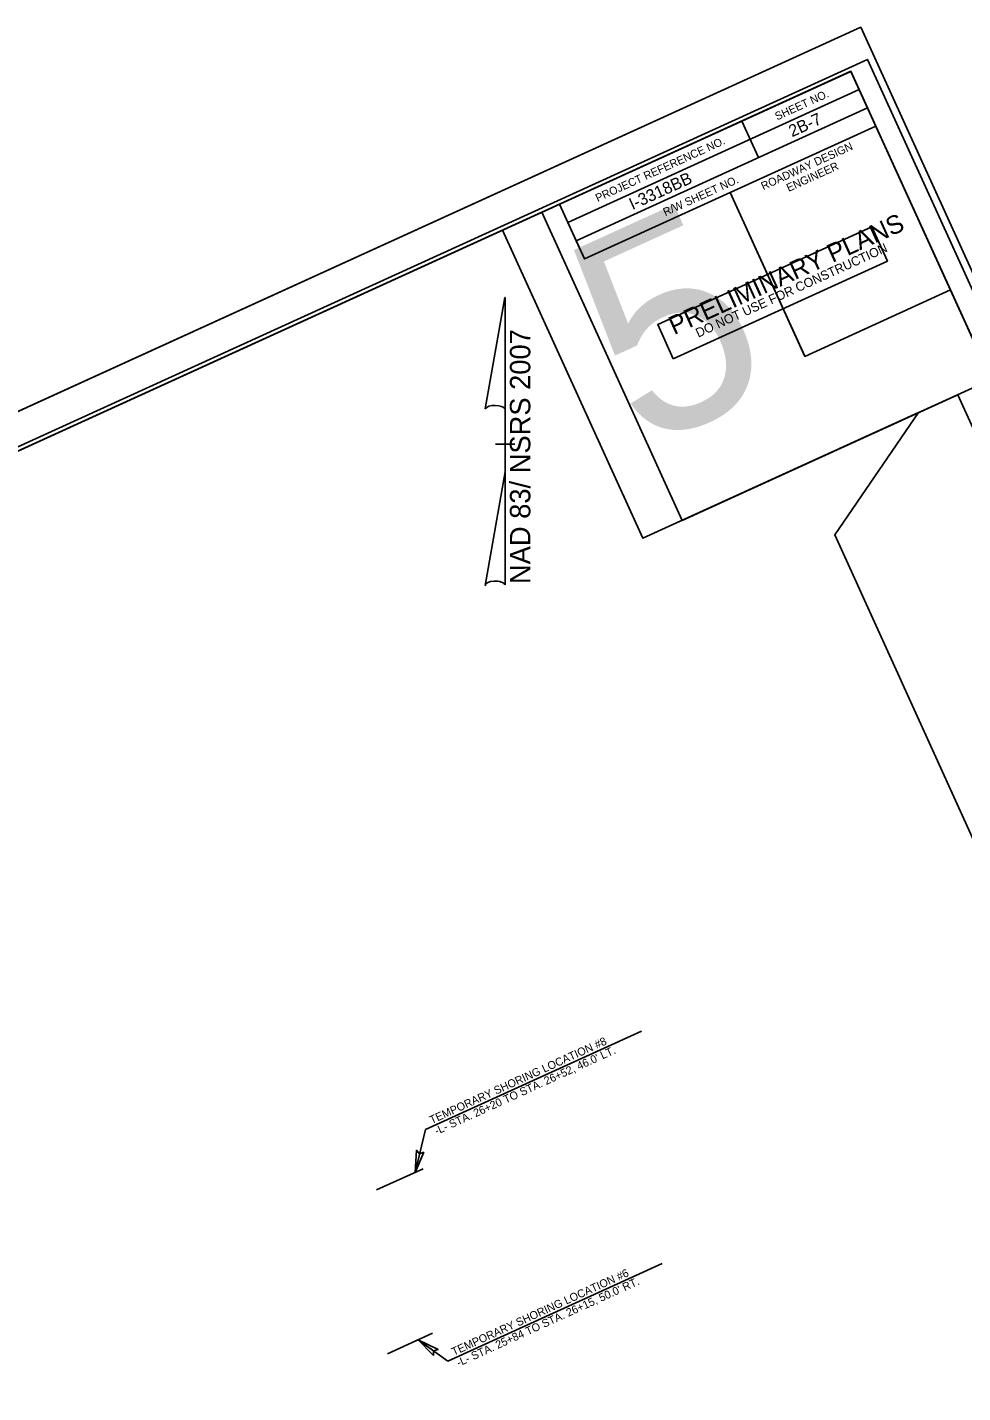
# Model space of a CAD drawing. Extents: x 2247910 to 2249896, y 662531 to 664261.
# Drawn here: x 2248921 to 2249505, y 663373 to 664226 of the extents above; entities that cross this region are included whole.
import ezdxf

# ---------------------------------------------------------------- set-up
doc = ezdxf.new("R2010")
doc.units = 0
for name, color, linetype in [('Prop North Arrow NAD83 for Plan Sheets CELL', 7, 'Continuous'), ('Prop Temporary Shoring', 7, 'Continuous'), ('Prop Temporary Shoring Leader Line', 7, 'Continuous'), ('Prop Terminator CELL', 7, 'Continuous'), ('Sheet Clip Boundary CELL', 7, 'Continuous'), ('Sheet Cutting Line CELL', 7, 'Continuous'), ('Sheet Data Field CELL', 7, 'Continuous'), ('Sheet Layout Plan Border', 7, 'Continuous'), ('Sheet Plan CELL', 7, 'Continuous'), ('Sheet Plan Layout CELL', 7, 'Continuous'), ('Sheet Plot Border Inside CELL', 7, 'Continuous'), ('Sheet Plot Border Outside CELL', 7, 'Continuous'), ('Sheet Sticker Preliminary CELL', 7, 'Continuous')]:
    doc.layers.add(name, color=color, linetype=linetype)

msp = doc.modelspace()

# ---------------------------------------------------------------- linework, layer by layer
at = {"layer": 'Prop North Arrow NAD83 for Plan Sheets CELL'}
for p, q in [((2249206.85, 663987.49), (2249219.15, 664057.02)), ((2249219.22, 664057.02), (2249219.15, 664057.02)), ((2249219.22, 664057.02), (2249219.15, 664057.02)), ((2249219.22, 664057.02), (2249219.22, 663985.32)), ((2249219.22, 663948.12), (2249219.22, 663987.42)), ((2249219.22, 663985.32), (2249219.22, 663987.34)), ((2249213.22, 663965.52), (2249213.15, 663965.52)), ((2249218.55, 663965.52), (2249213.22, 663965.52)), ((2249213.3, 663965.52), (2249225.3, 663965.52)), ((2249219.22, 663948.12), (2249206.7, 663877.24)), ((2249219.3, 663877.54), (2249219.22, 663948.12))]:
    msp.add_line(p, q, dxfattribs=at)
for centre, start_param, end_param in [((2249213.05, 663986.75), 0.216388, 2.908219), ((2249213.05, 663877), 0.201328, 3.141593)]:
    msp.add_ellipse(centre, major_axis=(6.35, -0.05), ratio=0.461098, start_param=start_param, end_param=end_param, dxfattribs=at)
at = {"layer": 'Prop Temporary Shoring'}
for p, q in [((2249138.82, 663499.62), (2249167.96, 663512.85)), ((2249145.75, 663397.32), (2249173.97, 663410.15))]:
    msp.add_line(p, q, dxfattribs=at)
at = {"layer": 'Prop Temporary Shoring Leader Line'}
for p, q in [((2249169.59, 663537.33), (2249304.54, 663598.83)), ((2249169.59, 663537.33), (2249162.98, 663510.59)), ((2249183.4, 663392.55), (2249317.41, 663453.62)), ((2249183.4, 663392.55), (2249164.97, 663406.05))]:
    msp.add_line(p, q, dxfattribs=at)
at = {"layer": 'Prop Terminator CELL'}
for points in [[(2249168.48, 663523.14), (2249162.98, 663510.59), (2249163.91, 663524.35), (2249165.83, 663522.1)], [(2249174.49, 663396.2), (2249164.97, 663406.05), (2249177.34, 663399.97), (2249174.53, 663399.05)]]:
    msp.add_lwpolyline(points, close=True, dxfattribs=at)
at = {"layer": 'Sheet Clip Boundary CELL'}
msp.add_lwpolyline([(2248241.67, 663371.06), (2248514.44, 662770.57), (2248551.22, 662641.58), (2249825.2, 663222.11), (2249780.68, 663312.06), (2249743.43, 663294.89), (2249677.44, 663353.62), (2249425.27, 663908.72), (2249477.5, 663985.14), (2249305.27, 663906.66), (2249217.58, 664099.11), (2248115.83, 663597.06)], close=True, dxfattribs=at)
at = {"layer": 'Sheet Cutting Line CELL'}
msp.add_line((2249441.45, 664225.83), (2247909.5, 663527.75), dxfattribs=at)
at = {"layer": 'Sheet Layout Plan Border'}
msp.add_lwpolyline([(2248198.13, 663481.51), (2248575.77, 662652.77), (2249849.75, 663233.3), (2249502.05, 663996.33), (2249329.83, 663917.85), (2249242.13, 664110.3), (2248140.38, 663608.25)], close=True, dxfattribs=at)
at = {"layer": 'Sheet Plan CELL'}
for p, q in [((2249258.45, 664103.96), (2249440.49, 664186.9)), ((2249263.66, 664092.55), (2249445.68, 664175.52)), ((2249263.66, 664092.55), (2249445.68, 664175.52)), ((2249367.05, 664167.15), (2249377.46, 664144.42)), ((2249268.84, 664081.19), (2249359.88, 664122.68)), ((2249359.88, 664122.68), (2249406.53, 664020.34)), ((2249263.66, 664092.55), (2249268.84, 664081.19))]:
    msp.add_line(p, q, dxfattribs=at)
for points in [[(2249435.32, 664198.33), (2248070.33, 663576.33), (2248505.72, 662620.85), (2249870.7, 663242.85)], [(2249253.26, 664115.38), (2249435.32, 664198.33), (2249445.68, 664175.52), (2249263.66, 664092.55)], [(2249359.88, 664122.68), (2249450.86, 664164.15), (2249497.53, 664061.77), (2249406.53, 664020.29)], [(2248505.72, 662620.85), (2248070.31, 663576.29), (2249253.26, 664115.38), (2249268.84, 664081.19), (2249359.88, 664122.68), (2249406.53, 664020.29), (2249497.53, 664061.77), (2249870.7, 663242.85)]]:
    msp.add_lwpolyline(points, close=True, dxfattribs=at)
at = {"layer": 'Sheet Plan Layout CELL'}
for points in [[(2249305.27, 663906.66), (2249523.01, 664005.88), (2249435.34, 664198.34), (2249217.58, 664099.11)], [(2248070.31, 663576.29), (2248505.72, 662620.85), (2249870.68, 663242.84), (2249522.99, 664005.87), (2249305.27, 663906.66), (2249217.58, 664099.11)]]:
    msp.add_lwpolyline(points, close=True, dxfattribs=at)
at = {"layer": 'Sheet Plot Border Inside CELL'}
msp.add_lwpolyline([(2248367.09, 662554.92), (2249883.1, 663245.75), (2249445.65, 664205.77), (2247929.62, 663514.94)], close=True, dxfattribs=at)
at = {"layer": 'Sheet Plot Border Outside CELL'}
msp.add_lwpolyline([(2248363.56, 662531.33), (2249895.5, 663229.41), (2249441.45, 664225.83), (2247909.5, 663527.75)], close=True, dxfattribs=at)
at = {"layer": 'Sheet Sticker Preliminary CELL'}
msp.add_lwpolyline([(2249324.33, 664018.84), (2249314.59, 664040.22), (2249448.36, 664101.18), (2249458.1, 664079.79)], close=True, dxfattribs=at)

# ---------------------------------------------------------------- texts
at = {"layer": 'Prop North Arrow NAD83 for Plan Sheets CELL'}
msp.add_text('NAD 83/ NSRS 2007', height=12.75, rotation=90, dxfattribs=at).set_placement((2249235, 663878.07))
at = {"layer": 'Prop Temporary Shoring'}
for s, p in [('TEMPORARY SHORING LOCATION #8', (2249173.36, 663540.71)), ("-L- STA. 26+20 TO STA. 26+52, 46.0' LT.", (2249176.47, 663533.88)), ('TEMPORARY SHORING LOCATION #6', (2249187.17, 663395.92)), ("-L- STA. 25+84 TO STA. 26+15, 50.0' RT.", (2249190.28, 663389.1))]:
    msp.add_text(s, height=5, rotation=24.49794, dxfattribs=at).set_placement(p)
at = {"layer": 'Sheet Data Field CELL'}
for s, p in [('2B-7', (2249398.54, 664157.12)), ('I-3318BB', (2249298.8, 664111.6))]:
    msp.add_text(s, height=7.5, rotation=24.49795, dxfattribs=at).set_placement(p)
at = {"layer": 'Sheet Plan CELL'}
for s, height, p in [('SHEET NO.', 5, (2249389.2, 664167.62)), ('PROJECT REFERENCE NO.', 5.0001, (2249277.08, 664116.65)), ('ROADWAY DESIGN', 5.0001, (2249380.54, 664124.04)), ('ENGINEER', 5, (2249396.39, 664122.98)), ('R/W SHEET NO.', 5.0001, (2249319.34, 664107.83))]:
    msp.add_text(s, height=height, rotation=24.49795, dxfattribs=at).set_placement(p)
at = {"layer": 'Sheet Plan Layout CELL'}
msp.add_text('5 ', height=131.25, rotation=24.49794, dxfattribs=at).set_placement((2249303.42, 663961.22))
at = {"layer": 'Sheet Sticker Preliminary CELL'}
for s, height, p in [('PRELIMINARY PLANS', 11.52, (2249324.8, 664033.5)), ('DO NOT USE FOR CONSTRUCTION', 5.76, (2249339.91, 664031.92))]:
    msp.add_text(s, height=height, rotation=24.49794, dxfattribs=at).set_placement(p)

doc.saveas('drawing.dxf')
